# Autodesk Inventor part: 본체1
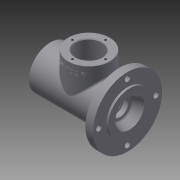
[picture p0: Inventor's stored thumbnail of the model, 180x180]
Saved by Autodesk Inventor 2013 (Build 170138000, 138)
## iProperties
Created: 2016-08
Part Number: 본체1
Material: 일반
Document SubType Name: Modeling
Designer: Administrator
Density: 1 g/cm^3
Author: Administrator
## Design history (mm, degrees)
sketch "스케치1"
  geometry: L1 (0, 0)-(115, 0); L2 (0, 0)-(0, 31); L3 (0, 31)-(99, 31); L4 (99, 31)-(99, 50); L5 (99, 50)-(112, 50); L6 (112, 50)-(112, 31); L7 (112, 31)-(115, 31); L8 (115, 0)-(115, 31)
  constraints: 16 end point, 4 horizontal, 4 vertical
  dimensions: "d0" = 115 distance of L1.start L1.end; "d1" = 62 diameter of L7 L1; "d2" = 100 diameter of L5 L1; "d3" = 62 diameter of L3 L1; "d4" = 13 distance between parallel lines of L6 L4; "d5" = 3 distance between parallel lines of L8 L6
revolve "회전1" sketch "스케치1" stored, may be unused: angle "d6" = 90 deg
sketch "스케치2"
  geometry: L1 (0, -31)-(0, 31) reference; L2 (115, -31)-(115, 31) reference; L3 (9, 0)-(9, 24); L4 (9, 24)-(12, 24); L5 (12, 24)-(12, 0); L6 (12, 20)-(21, 20); L7 (21, 20)-(21, 0); L8 (21, 17.5)-(25.003, 17.5); L9 (25.003, 17.5)-(25.003, 0); L10 (25.003, 18.5)-(26.753, 18.5); L11 (26.753, 18.5)-(26.753, 0); L12 (26.753, 18.5)-(26.753, 17.5); L13 (26.753, 17.5)-(37, 17.5); L14 (37, 17.5)-(37, 0); L15 (37, 17.5)-(37, 26); L16 (37, 26)-(75, 26); L17 (75, 26)-(75, 0); L18 (75, 17.5)-(86, 17.5); L19 (86, 17.5)-(86, 0); L20 (86, 16.5)-(91, 16.5); L21 (91, 16.5)-(91, 0); L22 (91, 10)-(93.7, 10); L23 (93.7, 10)-(93.7, 0); L24 (101, 16)-(115, 21); L25 (115, 21)-(115, 0); L26 (93.7, 12.5)-(101, 12.5); L27 (101, 12.5)-(101, 16); L28 (101, 12.5)-(101, 0); L29 (25.003, 17.5)-(25.003, 18.5); L30 (93.7, 10)-(93.7, 12.5); L31 (0, 31)-(99, 31) reference; L32 (0, 33.865)-(56, 33.865); L33 (56, 33.865)-(56, 16); L34 (0, 31)-(0, 33.865); 1 further point
  constraints: 62 end point, 19 vertical, 10 horizontal, 8 point on line, 1 midpoint, 15 other
  dimensions: "d7" = 48 dimension on L4; "d9" = 40 dimension on L6; "d10" = 35 dimension on L8; "d11" = 35 dimension on L13; "d12" = 37 dimension on L10; "d13" = 52 dimension on L16; "d14" = 35 dimension on L18; "d15" = 33 dimension on L20; "d17" = 20 dimension on L22; "d20" = 42 dimension on L24.end; "d22" = 25 dimension on L26; "d23" = 32 dimension on L24.start; "d24" = 14 distance between parallel lines of L2 L27; "d25" = 3 distance between parallel lines of L5 L3; "d26" = 21 distance between parallel lines of L7 L1; "d27" = 12 distance between parallel lines of L5 L1; "d29" = 26.7525 distance between parallel lines of L1 L11; "d30" = 1.75 distance of L10.start L10.end; "d31" = 38 distance between parallel lines of L17 L14; "d32" = 86 distance between parallel lines of L1 L19; "d33" = 7.3 distance between parallel lines of L27 L23; "d34" = 2.7 distance between parallel lines of L23 L21; "d95" = 56 distance of L32.start L32.end
revolve "회전2" sketch "스케치2" stored, may be unused: angle "d35" = 90 deg
hole "구멍1" diameter "d38" = 40.376; stored, may be unused: countersink angle "d42" = 90 deg, drill point angle "d44" = 0 deg; dims "d36" = 10, "d37" = 10, "d39" = 6, "d40" = 4, "d41" = 2, "d43" = 9
node "작업 평면1"
sketch "스케치3"
  geometry: L1 (-105.5, -31)-(-105.5, 31) reference; L2 (-105.5, 0)-(-49.5, 0); C1 r 30 at (-49.5, 0)
  constraints: 2 end point, 1 centre point, 1 coincident, 1 horizontal
  dimensions: "d45" = 56 distance of L2.start L2.end; "d46" = 60 diameter of C1
extrude "돌출1" join sketch "스케치3" stored distance "d47" = 10; taper "d48" = 0 deg
hole "구멍2" diameter "d51" = 38; stored, may be unused: countersink angle "d55" = 90 deg, drill point angle "d57" = 0 deg; dims "d49" = 10, "d50" = 10, "d52" = 6, "d53" = 4, "d54" = 2, "d56" = 9
sketch "스케치4" dims "d58" = 48
  geometry: L1 (0, 0)-(0, 24); C1 r 19 at (0, 0) reference; C2 r 30 at (0, 0) reference; 2 further points
  constraints: 2 coincident, 2 end point, 1 vertical, 1 vertical alignment, 2 other
hole "구멍3" sketch "스케치4" at (0, 24) diameter "d59" = 3.242; stored, may be unused: countersink angle "d63" = 90 deg, drill point angle "d65" = 0 deg; dims "d60" = 8, "d61" = 4, "d62" = 2, "d64" = 10
sketch "스케치5" dims "d69" = 83
  geometry: L1 (0, 0)-(0, 41.5); C1 r 31 at (0, 0) reference; C2 r 50 at (0, 0) reference; 2 further points
  constraints: 2 coincident, 2 end point, 1 vertical, 1 vertical alignment, 2 other
hole "구멍4" sketch "스케치5" at (0, 41.5) diameter "d70" = 8; stored, may be unused: countersink angle "d74" = 90 deg, drill point angle "d76" = 0 deg; dims "d71" = 8, "d72" = 4, "d73" = 2, "d75" = 10
fillet "모깎기1" dims "d80" = 3
fillet "모깎기2" dims "d81" = 3
fillet "모깎기3" dims "d82" = 0.3
chamfer "모따기1" distance "d83" = 0.7; stored, may be unused: second distance "d84" = 2, angle "d85" = 30 deg
chamfer "모따기2" distance "d86" = 1; stored, may be unused: second distance "d87" = 2, angle "d88" = 45 deg
node "작업 평면2"
sketch "스케치6"
  geometry: L1 (-30, 0)-(30, 0) reference; L2 (0, 0)-(0, -10); L3 (-20.739, -6.998)-(20.739, -6.998); L4 (20.739, -6.998)-(20.739, -13.002); L5 (20.739, -13.002)-(-20.739, -13.002); L6 (-20.739, -13.002)-(-20.739, -6.998); L7 (-20.739, -13.002)-(20.739, -6.998); 1 further point
  constraints: 4 end point, 2 midpoint, 1 vertical, 2 other
  dimensions: "d89" = 10 distance of L2.end L2.start
feature "엠보싱1" sketch "스케치6" dims "d90" = 0.5, "d91" = 0
chamfer "모따기3" distance "d92" = 1; stored, may be unused: second distance "d93" = 2, angle "d94" = 45 deg
fillet "모깎기4" dims "d96" = 3
node "솔리드1"
pattern_circular "원형 패턴1" dims angle "d67" = 360 deg
pattern_circular "원형 패턴2" dims angle "d78" = 360 deg
node "투영된 루프1"
node "투영된 루프2"
